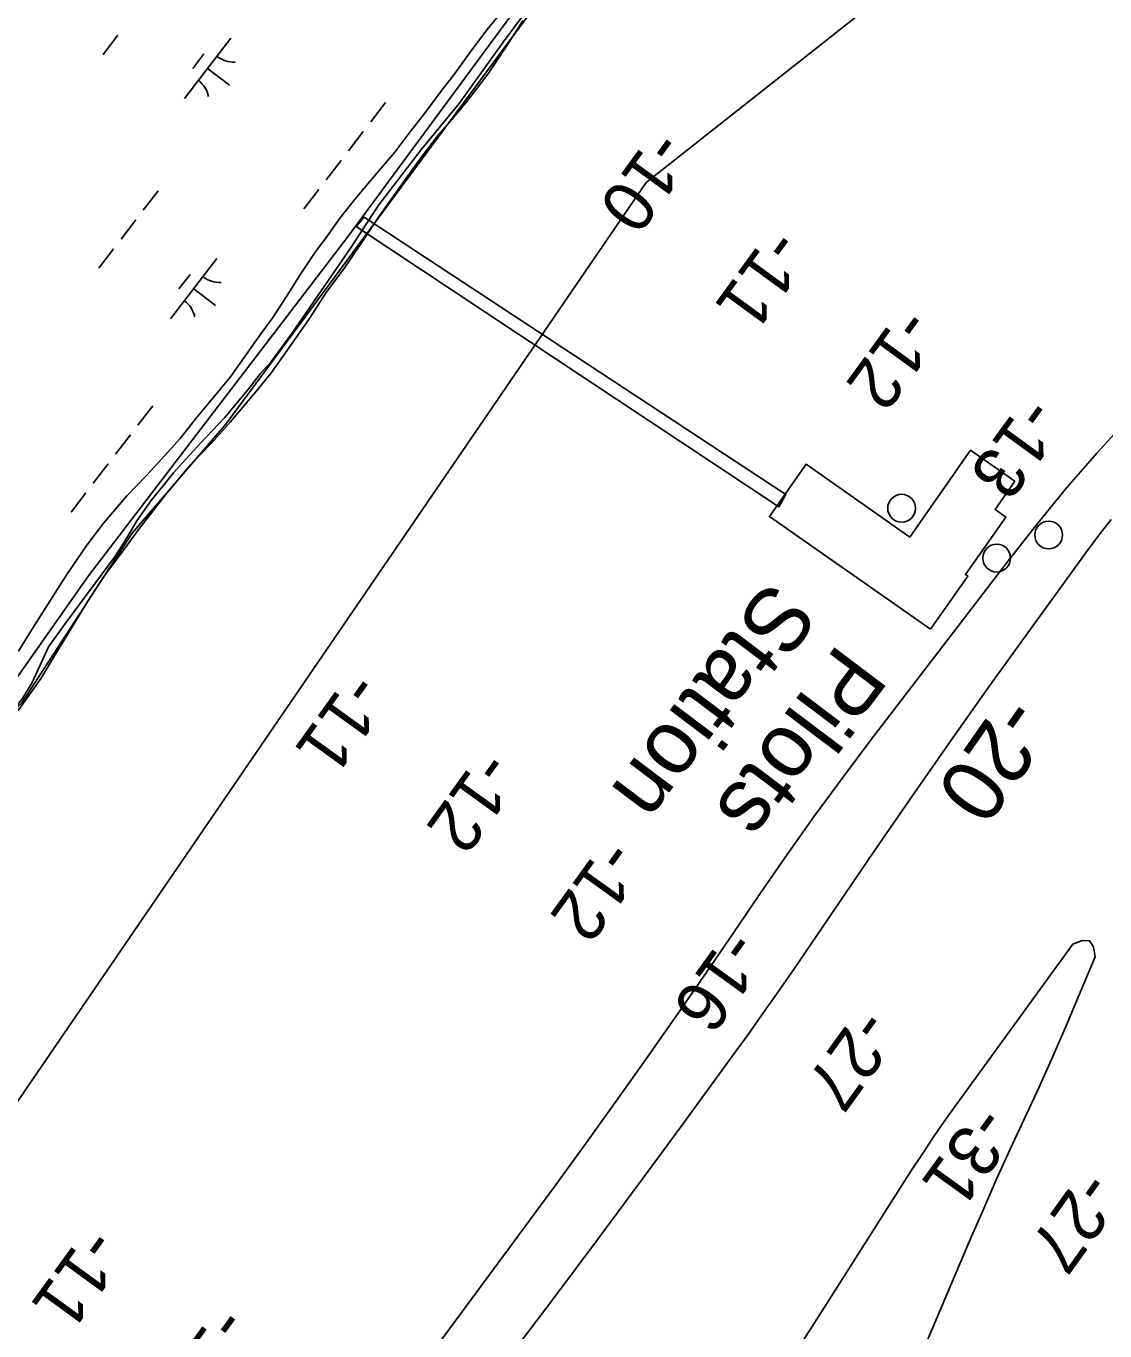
# Model space of a CAD drawing. Extents: x 3879599 to 3900814, y 146526 to 168888.
# Drawn here: x 3894372 to 3895080, y 161718 to 162574 of the extents above; entities that cross this region are included whole.
import ezdxf

# ---------------------------------------------------------------- set-up
doc = ezdxf.new("R2010")
doc.units = 0
for name, color, linetype in [('V-BLDG-IDEN', 7, 'Continuous'), ('V-BLDG-OTLN', 7, 'Continuous'), ('V-CHAN-DOCK', 7, 'Continuous'), ('V-DOMW-TANK', 7, 'Continuous'), ('V-RIVR-EDGE', 7, 'Continuous'), ('V-RIVR-JETY', 7, 'Continuous'), ('V-RIVR-RANG', 7, 'Continuous'), ('V-RRAP-FSHR', 7, 'Continuous'), ('V-TOPO-DPTH', 7, 'Continuous'), ('V-TOPO-MINR', 7, 'Continuous'), ('V-TOPO-MINR-IDEN', 7, 'Continuous'), ('V-WETL-SWMP', 7, 'Continuous')]:
    doc.layers.add(name, color=color, linetype=linetype)

msp = doc.modelspace()

# ---------------------------------------------------------------- linework, layer by layer
at = {"layer": 'V-BLDG-OTLN'}
msp.add_lwpolyline([(3894965.75, 162178.5), (3894860.02, 162252.46), (3894884.03, 162286.78), (3894952.27, 162239.05), (3894992.08, 162295.97), (3895021.18, 162275.62), (3895008.21, 162257.08), (3895015.21, 162252.18), (3894988.8, 162214.4), (3894990.18, 162213.43)], close=True, dxfattribs=at)
at = {"layer": 'V-CHAN-DOCK'}
msp.add_lwpolyline([(3894588.56, 162442.89), (3894866.23, 162258.78), (3894870.72, 162267.01), (3894593.8, 162448.88)], close=True, dxfattribs=at)
at = {"layer": 'V-DOMW-TANK'}
for centre in [(3894946.76, 162257.94), (3895043.31, 162240.37), (3895009.16, 162225.19)]:
    msp.add_circle(centre, 9.12, dxfattribs=at)
at = {"layer": 'V-RIVR-EDGE'}
msp.add_lwpolyline([(3894996.77, 162983.53), (3894972.23, 162947.83), (3894959.22, 162908.81), (3894952.72, 162865.13), (3894942.49, 162837.26), (3894932.27, 162822.39), (3894915.55, 162820.53), (3894892.32, 162812.17), (3894875.59, 162806.59), (3894862.58, 162797.3), (3894686.03, 162560.35), (3894502.98, 162313.18), (3894441.65, 162241.63), (3894369.17, 162130.13), (3894334.79, 162095.75), (3894315.28, 162075.3), (3893894.35, 161523.35), (3893644.39, 161210.21), (3893630.45, 161202.78), (3893449.25, 161162.82), (3893262.48, 161121.94), (3892618.54, 160989.06), (3892386.24, 160942.6)], dxfattribs=at)
at = {"layer": 'V-RIVR-JETY'}
for points in [[(3894721.45, 162612.7), (3894685.15, 162563.89), (3894656.19, 162523.56), (3894631.73, 162493.72), (3894603.6, 162457.02), (3894584.42, 162427.97), (3894546.46, 162372.7), (3894532.6, 162353.74), (3894525.67, 162346.08), (3894518.33, 162336.81), (3894502.44, 162317.46), (3894494.3, 162309), (3894486.56, 162300.94), (3894476.79, 162290.06), (3894468.64, 162281.19), (3894461.71, 162272.32), (3894453.97, 162263.05), (3894444.58, 162249.74), (3894438.04, 162238.43), (3894430.69, 162226.73), (3894397.25, 162181.96), (3894386.65, 162167.04)], [(3894684.48, 162584.2), (3894674.66, 162572.13), (3894665.85, 162560.4), (3894652.29, 162541.63), (3894644.83, 162532.24), (3894635, 162518.84), (3894622.47, 162503.08), (3894613.99, 162491.69), (3894603.83, 162479.63), (3894595.03, 162469.24), (3894587.24, 162460.19), (3894578.77, 162449.47), (3894568.6, 162435.05), (3894561.82, 162426), (3894551.98, 162411.58), (3894542.82, 162396.82), (3894533.99, 162383.07), (3894523.82, 162369.33), (3894515.01, 162356.92), (3894506.19, 162344.18), (3894493.32, 162328.77), (3894483.5, 162317.04), (3894473, 162303.64), (3894460.81, 162290.24), (3894450.99, 162279.52), (3894438.13, 162266.13), (3894422.89, 162248.38), (3894411.71, 162233.62), (3894398.14, 162213.84), (3894384.91, 162192.71), (3894376.08, 162178.96), (3894366.92, 162164.2)], [(3894386.65, 162167.04), (3894382.14, 162157.34), (3894375.58, 162143.2), (3894369.87, 162133.52), (3894363.34, 162125.05), (3894356.01, 162116.18), (3894348.27, 162107.71), (3894337.69, 162097.24), (3894330.35, 162089.59), (3894321.4, 162081.13), (3894314.07, 162073.07), (3894307.56, 162065.82), (3894301.85, 162059.77), (3894292.08, 162049.3), (3894283.94, 162041.24), (3894242.81, 161997.73), (3894214.67, 161960.63), (3894186.93, 161921.5), (3894149.81, 161870.27), (3894122.88, 161830.33), (3894086.19, 161783.55), (3894047.03, 161729.5), (3893995.26, 161665.79)]]:
    msp.add_lwpolyline(points, dxfattribs=at)
at = {"layer": 'V-RRAP-FSHR'}
msp.add_lwpolyline([(3894988.6, 162989.5), (3894928.15, 162903.5), (3894582.92, 162435.83), (3894412.91, 162213.52), (3894350.95, 162125.82), (3894296.72, 162068.74), (3894092.54, 161803.48), (3893724.45, 161331), (3893640.54, 161218.2), (3893416.13, 161165.56), (3892609.14, 161000)], dxfattribs=at)
at = {"layer": 'V-TOPO-DPTH'}
for points in [[(3894583.39, 161564.9), (3894255.7, 161739.59), (3894330.09, 161816.04), (3894779.1, 162471.69), (3894959.67, 162614.35), (3894982.55, 162633.86), (3895004.38, 162654.41), (3895024.63, 162676.51), (3895043.83, 162699.66), (3895072.99, 162737.61), (3895076.66, 162742.66), (3895080.14, 162747.83), (3895083.35, 162753.17), (3895086.37, 162758.63), (3895101.79, 162788.37), (3895104.27, 162794.7), (3895105.86, 162801.16), (3895106.1, 162807.8), (3895105.44, 162814.57), (3895407.09, 162684.23)], [(3895084.31, 162250.64), (3895077.08, 162241.29), (3895070.01, 162231.8), (3895031.35, 162178.54), (3895005.23, 162142.21), (3894979.33, 162105.74), (3894953.74, 162069.04), (3894928.36, 162032.2), (3894876.13, 161955.66), (3894866.19, 161941.25), (3894856.17, 161926.91), (3894846.01, 161912.66), (3894835.76, 161898.48), (3894801.73, 161851.87), (3894774.27, 161814.52), (3894746.65, 161777.29), (3894718.78, 161740.25), (3894690.75, 161703.33), (3894651.28, 161651.69), (3894634.47, 161629.86), (3894617.57, 161608.11), (3894600.53, 161586.47), (3894583.39, 161564.9)], [(3894690.75, 161703.33), (3894718.78, 161740.25), (3894746.65, 161777.29), (3894774.27, 161814.52), (3894801.73, 161851.87), (3894835.76, 161898.48), (3894846.01, 161912.66), (3894856.17, 161926.91), (3894866.19, 161941.25), (3894876.13, 161955.66), (3894928.36, 162032.2), (3894953.74, 162069.04), (3894979.33, 162105.74), (3895005.23, 162142.21), (3895031.35, 162178.54), (3895070.01, 162231.8), (3895077.08, 162241.29), (3895084.31, 162250.64)], [(3895008.96, 161817.09), (3895018.15, 161837.29), (3895027.49, 161857.42), (3895036.79, 161877.57), (3895045.91, 161897.8), (3895054.76, 161918.15), (3895063.41, 161938.59), (3895073.78, 161963.54), (3895072.68, 161970.14), (3895070.12, 161974.14), (3895065.37, 161974.24), (3895059.16, 161971.75), (3894984.3, 161868.85), (3894976.32, 161857.66), (3894968.47, 161846.38), (3894960.83, 161834.96), (3894953.33, 161823.44), (3894897.57, 161736.06), (3894873.53, 161698.37)], [(3895008.96, 161817.09), (3895018.15, 161837.29), (3895027.49, 161857.42), (3895036.79, 161877.57), (3895045.91, 161897.8), (3895054.76, 161918.15), (3895063.41, 161938.59), (3895073.78, 161963.54), (3895072.68, 161970.14), (3895070.12, 161974.14), (3895065.37, 161974.24), (3895059.16, 161971.75), (3894984.3, 161868.85), (3894976.32, 161857.66), (3894968.47, 161846.38), (3894960.83, 161834.96), (3894953.33, 161823.44), (3894897.57, 161736.06), (3894873.53, 161698.37)], [(3894770.14, 161131.82), (3894720.32, 161168.03), (3894735.27, 161195.39), (3894756.31, 161235.18), (3894776.61, 161275.32), (3894795.81, 161316), (3894814.28, 161357.04), (3894833.42, 161401.18), (3894841.71, 161420.44), (3894849.91, 161439.74), (3894858.01, 161459.08), (3894866.02, 161478.46), (3894881.42, 161516.02), (3894897.16, 161554.17), (3894913, 161592.28), (3894928.99, 161630.32), (3894945.1, 161668.32), (3894991.18, 161776.42), (3895000, 161796.79), (3895008.96, 161817.09)], [(3894945.1, 161668.32), (3894991.18, 161776.42), (3895000, 161796.79), (3895008.96, 161817.09)]]:
    msp.add_lwpolyline(points, dxfattribs=at)
at = {"layer": 'V-TOPO-MINR'}
for points in [[(3894959.67, 162614.35), (3894779.1, 162471.69), (3894330.09, 161816.04), (3894255.7, 161739.59)], [(3895095.46, 162316.5), (3895075.18, 162294.19), (3895055.35, 162271.5), (3895036.21, 162248.22), (3895017.53, 162224.56), (3894926.79, 162106.08), (3894908.08, 162081.2), (3894889.66, 162056.11), (3894871.68, 162030.7), (3894854, 162005.07), (3894836.47, 161979.34), (3894818.85, 161953.67), (3894801.09, 161928.1), (3894783.24, 161902.58), (3894779.63, 161897.46), (3894759.81, 161869.51), (3894739.85, 161841.65), (3894719.7, 161813.93), (3894699.42, 161786.31), (3894593.7, 161643.39)], [(3895084.31, 162250.64), (3895077.08, 162241.29), (3895070.01, 162231.8), (3895031.35, 162178.54), (3895005.23, 162142.21), (3894979.33, 162105.74), (3894953.74, 162069.04), (3894928.36, 162032.2), (3894876.13, 161955.66), (3894866.19, 161941.25), (3894856.17, 161926.91), (3894846.01, 161912.66), (3894835.76, 161898.48), (3894801.73, 161851.87), (3894774.27, 161814.52), (3894746.65, 161777.29), (3894718.78, 161740.25), (3894690.75, 161703.33)], [(3895008.96, 161817.09), (3895018.15, 161837.29), (3895027.49, 161857.42), (3895036.79, 161877.57), (3895045.91, 161897.8), (3895054.76, 161918.15), (3895063.41, 161938.59), (3895073.78, 161963.54), (3895072.68, 161970.14), (3895070.12, 161974.14), (3895065.37, 161974.24), (3895059.16, 161971.75), (3894984.3, 161868.85), (3894976.32, 161857.66), (3894968.47, 161846.38), (3894960.83, 161834.96), (3894953.33, 161823.44), (3894897.57, 161736.06), (3894873.53, 161698.37)], [(3894945.1, 161668.32), (3894991.18, 161776.42), (3895000, 161796.79), (3895008.96, 161817.09)]]:
    msp.add_lwpolyline(points, dxfattribs=at)
at = {"layer": 'V-WETL-SWMP'}
for p, q in [((3894688.16, 162562.48), (3894698.37, 162578.22)), ((3894432.18, 162568.45), (3894422.43, 162555.77)), ((3894506.34, 162566.43), (3894475.87, 162526.78)), ((3894675.1, 162542.7), (3894688.16, 162562.48)), ((3894488.64, 162556.06), (3894481.33, 162546.55)), ((3894491.1, 162546.6), (3894505.38, 162535.64)), ((3894661.23, 162524.96), (3894675.1, 162542.7)), ((3894607.94, 162524.19), (3894598.19, 162511.5)), ((3894652.67, 162514.47), (3894661.23, 162524.96)), ((3894641.67, 162501.57), (3894652.67, 162514.47)), ((3894593.32, 162505.16), (3894583.57, 162492.47)), ((3894629.43, 162485.43), (3894641.67, 162501.57)), ((3894578.7, 162486.13), (3894568.95, 162473.44)), ((3894603.72, 162449.52), (3894629.43, 162485.43)), ((3894458.61, 162466.22), (3894448.86, 162453.54)), ((3894564.07, 162467.1), (3894554.32, 162454.41)), ((3894443.99, 162447.19), (3894434.24, 162434.51)), ((3894593.1, 162433.37), (3894603.72, 162449.52)), ((3894429.36, 162428.16), (3894419.61, 162415.48)), ((3894581.27, 162416.02), (3894593.1, 162433.37)), ((3894497.24, 162421.78), (3894466.78, 162382.13)), ((3894479.55, 162411.41), (3894472.24, 162401.9)), ((3894569.03, 162399.48), (3894581.27, 162416.02)), ((3894482.01, 162401.95), (3894496.28, 162390.98)), ((3894558, 162382.53), (3894569.03, 162399.48)), ((3894544.13, 162362.75), (3894558, 162382.53)), ((3894533.11, 162347.01), (3894544.13, 162362.75)), ((3894523.73, 162335.32), (3894533.11, 162347.01)), ((3894505.8, 162314.35), (3894523.73, 162335.32)), ((3894455.03, 162325.2), (3894445.28, 162312.52)), ((3894493.57, 162300.64), (3894505.8, 162314.35)), ((3894440.4, 162306.17), (3894430.66, 162293.49)), ((3894479.72, 162286.14), (3894493.57, 162300.64)), ((3894425.78, 162287.14), (3894416.03, 162274.46)), ((3894463.42, 162266.78), (3894479.72, 162286.14)), ((3894411.16, 162268.11), (3894401.41, 162255.43)), ((3894445.88, 162244.19), (3894463.42, 162266.78)), ((3894434.05, 162228.05), (3894445.88, 162244.19)), ((3894423.04, 162213.13), (3894434.05, 162228.05)), ((3894412.42, 162196.98), (3894423.04, 162213.13)), ((3894391.18, 162162.26), (3894412.42, 162196.98)), ((3894381.78, 162146.51), (3894391.18, 162162.26)), ((3894366.68, 162125.13), (3894381.78, 162146.51))]:
    msp.add_line(p, q, dxfattribs=at)
for centre, start, end in [((3894508.12, 162568.36), 231.68688, 273.23054), ((3894474.46, 162524.56), 11.68688, 53.23054), ((3894499.03, 162423.71), 231.68688, 273.23054), ((3894465.37, 162379.91), 11.68688, 53.23054)]:
    msp.add_arc(centre, 17.62, start, end, dxfattribs=at)

# ---------------------------------------------------------------- texts
at = {"layer": 'V-BLDG-IDEN'}
for s, p in [('Station', (3894859.9, 162212.19)), ('Pilots', (3894905.44, 162170.29))]:
    msp.add_text(s, height=42, rotation=232.99246, dxfattribs=at).set_placement(p)
at = {"layer": 'V-RIVR-RANG'}
for s, rotation, p in [('-10', 233.94833, (3894784.81, 162507.99)), ('-11', 233.94833, (3894861.46, 162443.36)), ('-12', 233.94833, (3894947.34, 162391.43)), ('-13', 233.94833, (3895028.49, 162332.99)), ('-11', 234.20833, (3894585.4, 162152.33)), ('-12', 234.20833, (3894671.51, 162100.79)), ('-12', 234.20833, (3894752.77, 162042.51)), ('-16', 234.20833, (3894833.26, 161983.16)), ('-27', 234.20833, (3894919.46, 161931.72)), ('-31', 234.20833, (3894996.79, 161867.98)), ('-27', 234.35069, (3895066.11, 161825.27)), ('-11', 233.97833, (3894412.46, 161787.76)), ('-12', 233.97833, (3894498.37, 161735.87))]:
    msp.add_text(s, height=33.5, rotation=rotation, dxfattribs=at).set_placement(p)
at = {"layer": 'V-TOPO-MINR-IDEN'}
msp.add_text('-20', height=41.5, rotation=235.10977, dxfattribs=at).set_placement((3895013.99, 162137.31))

doc.saveas('drawing.dxf')
